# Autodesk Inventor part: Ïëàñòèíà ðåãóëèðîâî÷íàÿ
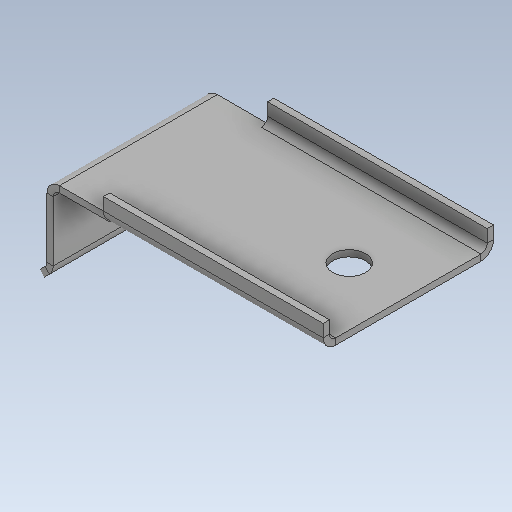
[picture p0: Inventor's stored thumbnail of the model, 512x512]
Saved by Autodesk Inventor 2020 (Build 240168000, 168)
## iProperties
Created: 1900-01
Part Number: Ïëàñòèíà ðåãóëèðîâî÷íàÿ
Material: Générique
Document SubType Name: Modeling
Designer: bruno
Density: 1 g/cm^3
Appearance: Par défaut
Author: bruno
Revision Number: ANYUNSPECIFIED
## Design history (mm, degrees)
feature "Base1"
node "Solide1"
